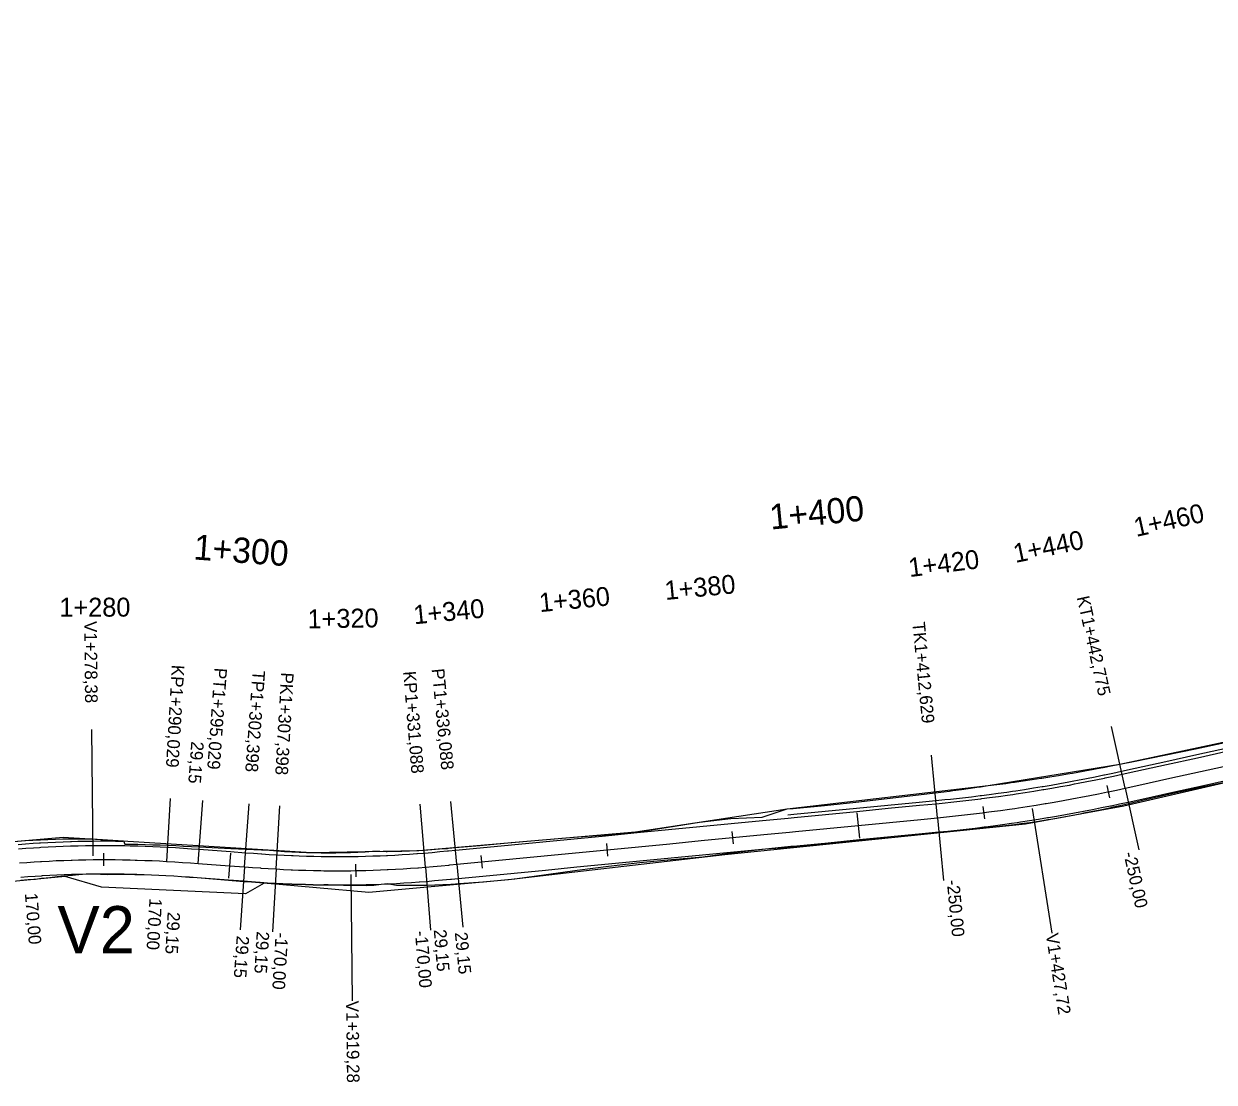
# Model space of a CAD drawing. Extents: x -636600 to -628587, y -1090963 to -1085869.
# Drawn here: x -634006.6 to -633817.9, y -1089449.3 to -1089281.6 of the extents above; entities that cross this region are included whole.
import ezdxf

# ---------------------------------------------------------------- set-up
doc = ezdxf.new("R2010")
doc.units = 0
for name, color, linetype in [('01_PARCELY_NÁVRH_PC', 7, 'Continuous'), ('03_PC_OBJEKTY_NÁVRH', 7, 'Continuous'), ('dno příkopu', 7, 'Continuous'), ('HEKTOMETRY100', 7, 'Continuous'), ('HEKTOMETRY20', 7, 'Continuous'), ('HL_BODY', 7, 'Continuous'), ('POLOMERY', 7, 'Continuous'), ('situace_osa', 7, 'Continuous'), ('situace_těleso', 7, 'Continuous'), ('situace_vozovka', 7, 'Continuous'), ('VRCHOLY', 7, 'Continuous')]:
    doc.layers.add(name, color=color, linetype=linetype)

msp = doc.modelspace()

# ---------------------------------------------------------------- linework, layer by layer
at = {"layer": '01_PARCELY_NÁVRH_PC'}
for points in [[(-634103.9, -1089419.55), (-634000.36, -1089410.49), (-633960.99, -1089412.95), (-633943.98, -1089412.6), (-633909.64, -1089409.67), (-633885.57, -1089406.01), (-633853.75, -1089402.34), (-633832.85, -1089398.94), (-633799.12, -1089391.77), (-633783.13, -1089387.75), (-633755.75, -1089378.34), (-633672.51, -1089347.22), (-633662.62, -1089342.52), (-633643.61, -1089332.07), (-633633.59, -1089327.63), (-633598.11, -1089315.12), (-633586.88, -1089310.55), (-633575.45, -1089304.31), (-633538.21, -1089281.62)], [(-633542.71, -1089289.87), (-633580.4, -1089312.77), (-633588.21, -1089316.5), (-633632.76, -1089332.36), (-633641.37, -1089336.22), (-633665.47, -1089349.24), (-633670.13, -1089353.9), (-633687.51, -1089361.23), (-633694.12, -1089361.51), (-633765.25, -1089388.16), (-633784.63, -1089394.62), (-633832.24, -1089405.6), (-633847.83, -1089408.44), (-633895.46, -1089413.28), (-633929.79, -1089417.29), (-633951.89, -1089419.25), (-633968.5, -1089417.82), (-633971.45, -1089419.48), (-633994.3, -1089418.42), (-634000.04, -1089416.76), (-634012.79, -1089417.95)]]:
    msp.add_lwpolyline(points, dxfattribs=at)
at = {"layer": 'dno příkopu'}
for points in [[(-633885.47, -1089406.97), (-633884.56, -1089406.88), (-633879.58, -1089406.4), (-633874.6, -1089405.92), (-633869.63, -1089405.44), (-633864.65, -1089404.96), (-633862.03, -1089404.7), (-633860.62, -1089404.56), (-633859.7, -1089404.47), (-633859.21, -1089404.41), (-633857.8, -1089404.26), (-633856.39, -1089404.09), (-633854.98, -1089403.92), (-633854.79, -1089403.89), (-633853.57, -1089403.74), (-633852.16, -1089403.55), (-633850.76, -1089403.35), (-633849.89, -1089403.22), (-633849.35, -1089403.15), (-633847.95, -1089402.93), (-633846.55, -1089402.71), (-633845.15, -1089402.48), (-633845, -1089402.46), (-633843.75, -1089402.24), (-633842.35, -1089402), (-633840.95, -1089401.74), (-633840.14, -1089401.59), (-633839.56, -1089401.48), (-633838.16, -1089401.21), (-633836.77, -1089400.93), (-633835.38, -1089400.65), (-633835.29, -1089400.63), (-633833.99, -1089400.35), (-633832.6, -1089400.05), (-633830.43, -1089399.57), (-633825.55, -1089398.5), (-633820.66, -1089397.42), (-633815.78, -1089396.35)], [(-634007.5, -1089411.66), (-634006.32, -1089411.57), (-634005.13, -1089411.48), (-634004.12, -1089411.42), (-634003.94, -1089411.41), (-634002.76, -1089411.34), (-634001.57, -1089411.29), (-634000.38, -1089411.24), (-633999.2, -1089411.19), (-633999.04, -1089411.19), (-633998.01, -1089411.16), (-633996.82, -1089411.14), (-633995.63, -1089411.12), (-633994.45, -1089411.11), (-633993.96, -1089411.11), (-633993.26, -1089411.11), (-633992.07, -1089411.12), (-633990.88, -1089411.13)]]:
    msp.add_lwpolyline(points, dxfattribs=at)
at = {"layer": 'HEKTOMETRY100'}
for points in [[(-633874.53, -1089406.66), (-633874.15, -1089410.65)], [(-633973.84, -1089413.04), (-633974.13, -1089417.03)]]:
    msp.add_lwpolyline(points, dxfattribs=at)
at = {"layer": 'HEKTOMETRY20'}
for points in [[(-633834.93, -1089402.34), (-633834.52, -1089404.3)], [(-633854.57, -1089405.63), (-633854.32, -1089407.61)], [(-633894.34, -1089409.59), (-633894.15, -1089411.58)], [(-633914.25, -1089411.51), (-633914.06, -1089413.5)], [(-633993.95, -1089413.06), (-633993.95, -1089415.06)], [(-633934.16, -1089413.43), (-633933.96, -1089415.43)], [(-633954.02, -1089414.81), (-633953.99, -1089416.81)]]:
    msp.add_lwpolyline(points, dxfattribs=at)
at = {"layer": 'HL_BODY'}
for points in [[(-633832.01, -1089402.74), (-633834.16, -1089392.97)], [(-633861.77, -1089407.44), (-633862.73, -1089397.49)], [(-633983.93, -1089414.34), (-633983.35, -1089404.36)], [(-633978.94, -1089414.68), (-633978.22, -1089404.7)], [(-633971.59, -1089415.21), (-633970.87, -1089405.24)], [(-633966.6, -1089415.55), (-633966.03, -1089405.56)], [(-633942.93, -1089415.26), (-633943.75, -1089405.3)], [(-633937.95, -1089414.81), (-633938.92, -1089404.85)]]:
    msp.add_lwpolyline(points, dxfattribs=at)
at = {"layer": 'POLOMERY'}
for points in [[(-633983.93, -1089414.34), (-633983.35, -1089404.36)], [(-633832.01, -1089402.74), (-633829.86, -1089412.5)], [(-633978.94, -1089414.68), (-633978.22, -1089404.7)], [(-633861.77, -1089407.44), (-633860.81, -1089417.39)], [(-633971.59, -1089415.21), (-633972.31, -1089425.18)], [(-633966.6, -1089415.55), (-633967.18, -1089425.53)], [(-633942.93, -1089415.26), (-633942.12, -1089425.23)], [(-633937.95, -1089414.81), (-633936.99, -1089424.76)]]:
    msp.add_lwpolyline(points, dxfattribs=at)
at = {"layer": 'situace_osa'}
msp.add_lwpolyline([(-634007.26, -1089414.6), (-634006.1, -1089414.51), (-634004.94, -1089414.43), (-634003.95, -1089414.37), (-634003.77, -1089414.36), (-634002.6, -1089414.29), (-634001.44, -1089414.23), (-634000.27, -1089414.18), (-633999.1, -1089414.14), (-633998.95, -1089414.14), (-633997.94, -1089414.11), (-633996.77, -1089414.09), (-633995.6, -1089414.07), (-633994.43, -1089414.06), (-633993.95, -1089414.06), (-633993.27, -1089414.06), (-633992.1, -1089414.07), (-633990.93, -1089414.08), (-633990.64, -1089414.09), (-633989.76, -1089414.1), (-633988.95, -1089414.13), (-633988.6, -1089414.14), (-633987.43, -1089414.18), (-633986.26, -1089414.22), (-633985.1, -1089414.28), (-633983.96, -1089414.34), (-633983.93, -1089414.34), (-633982.68, -1089414.42), (-633981.44, -1089414.5), (-633980.19, -1089414.59), (-633978.97, -1089414.68), (-633978.94, -1089414.68), (-633973.98, -1089415.04), (-633971.59, -1089415.21), (-633970.34, -1089415.3), (-633969.1, -1089415.39), (-633969, -1089415.4), (-633967.85, -1089415.47), (-633966.6, -1089415.55), (-633965.42, -1089415.61), (-633964.24, -1089415.67), (-633964, -1089415.68), (-633963.05, -1089415.72), (-633961.87, -1089415.76), (-633960.69, -1089415.79), (-633959.5, -1089415.81), (-633959.01, -1089415.82), (-633958.32, -1089415.82), (-633957.13, -1089415.83), (-633955.95, -1089415.83), (-633954.76, -1089415.82), (-633954.01, -1089415.81), (-633953.58, -1089415.8), (-633952.39, -1089415.77), (-633951.21, -1089415.74), (-633950.03, -1089415.7), (-633949.01, -1089415.65), (-633948.84, -1089415.64), (-633947.66, -1089415.58), (-633946.48, -1089415.52), (-633945.3, -1089415.44), (-633944.11, -1089415.36), (-633944.02, -1089415.35), (-633942.93, -1089415.26), (-633941.69, -1089415.16), (-633940.44, -1089415.04), (-633939.2, -1089414.93), (-633939.04, -1089414.91), (-633937.95, -1089414.81), (-633934.06, -1089414.43), (-633929.08, -1089413.95), (-633924.11, -1089413.47), (-633919.13, -1089412.99), (-633914.15, -1089412.51), (-633909.18, -1089412.02), (-633904.2, -1089411.54), (-633899.22, -1089411.06), (-633894.25, -1089410.58), (-633889.27, -1089410.1), (-633885.21, -1089409.71), (-633884.29, -1089409.62), (-633879.32, -1089409.14), (-633874.34, -1089408.66), (-633869.36, -1089408.17), (-633864.39, -1089407.69), (-633861.77, -1089407.44), (-633860.34, -1089407.3), (-633859.41, -1089407.2), (-633858.91, -1089407.15), (-633857.49, -1089406.99), (-633856.06, -1089406.82), (-633854.64, -1089406.65), (-633854.44, -1089406.62), (-633853.21, -1089406.46), (-633851.79, -1089406.27), (-633850.37, -1089406.07), (-633849.49, -1089405.95), (-633848.95, -1089405.86), (-633847.53, -1089405.65), (-633846.11, -1089405.43), (-633844.69, -1089405.19), (-633844.55, -1089405.17), (-633843.28, -1089404.95), (-633841.86, -1089404.7), (-633840.45, -1089404.45), (-633839.63, -1089404.29), (-633839.04, -1089404.18), (-633837.63, -1089403.91), (-633836.22, -1089403.63), (-633834.82, -1089403.34), (-633834.72, -1089403.32), (-633833.41, -1089403.04), (-633832.01, -1089402.74), (-633829.84, -1089402.26), (-633824.95, -1089401.18), (-633820.07, -1089400.11), (-633815.19, -1089399.03)], dxfattribs=at)
at = {"layer": 'situace_těleso'}
for points in [[(-634007.54, -1089411.14), (-634006.35, -1089411.05), (-634005.16, -1089410.98), (-634004.15, -1089410.93), (-634003.97, -1089410.92), (-634002.78, -1089410.87), (-634001.59, -1089410.83), (-634000.4, -1089410.79), (-633999.21, -1089410.77), (-633999.06, -1089410.77), (-633998.02, -1089410.76), (-633996.83, -1089410.76), (-633995.82, -1089410.78), (-633990.77, -1089411.09), (-633990.59, -1089411.59), (-633989.71, -1089411.6), (-633988.88, -1089411.62), (-633988.52, -1089411.63), (-633987.34, -1089411.66), (-633986.15, -1089411.7), (-633984.97, -1089411.74), (-633983.81, -1089411.79), (-633983.78, -1089411.79), (-633982.52, -1089411.85), (-633981.26, -1089411.92), (-633980, -1089411.98), (-633978.78, -1089412.04), (-633978.75, -1089412.04), (-633973.78, -1089412.28), (-633971.39, -1089412.39), (-633970.14, -1089412.45), (-633968.9, -1089412.51), (-633968.8, -1089412.51), (-633967.66, -1089412.57), (-633966.44, -1089412.67), (-633965.27, -1089412.76), (-633964.11, -1089412.83), (-633963.88, -1089412.84), (-633962.95, -1089412.88), (-633961.78, -1089412.93), (-633960.62, -1089412.96), (-633959.46, -1089412.98), (-633958.97, -1089412.98), (-633958.29, -1089412.99), (-633957.13, -1089412.98), (-633955.96, -1089412.96), (-633954.8, -1089412.93), (-633954.05, -1089412.9), (-633953.63, -1089412.88), (-633952.47, -1089412.82), (-633951.31, -1089412.75), (-633950.14, -1089412.75), (-633949.14, -1089412.77), (-633948.98, -1089412.76), (-633947.81, -1089412.74), (-633946.65, -1089412.71), (-633945.48, -1089412.67), (-633944.32, -1089412.62), (-633944.22, -1089412.61), (-633943.16, -1089412.55), (-633941.93, -1089412.47), (-633940.69, -1089412.38), (-633939.45, -1089412.28), (-633939.29, -1089412.27), (-633938.21, -1089412.17), (-633934.31, -1089411.82), (-633929.34, -1089411.35), (-633924.35, -1089410.93), (-633919.37, -1089410.5), (-633914.38, -1089410.13), (-633909.4, -1089409.71), (-633904.45, -1089408.92), (-633899.51, -1089408.13), (-633894.54, -1089407.56), (-633889.54, -1089407.35), (-633885.57, -1089406.01), (-633884.65, -1089405.94), (-633879.67, -1089405.5), (-633874.7, -1089404.95), (-633869.73, -1089404.37), (-633864.76, -1089403.79), (-633862.15, -1089403.48), (-633860.75, -1089403.31), (-633859.84, -1089403.2), (-633859.35, -1089403.13), (-633857.95, -1089402.94), (-633856.55, -1089402.75), (-633855.15, -1089402.54), (-633854.96, -1089402.51), (-633853.75, -1089402.34), (-633852.35, -1089402.17), (-633850.95, -1089401.98), (-633850.09, -1089401.87), (-633849.55, -1089401.8), (-633848.16, -1089401.6), (-633846.76, -1089401.39), (-633845.36, -1089401.17), (-633845.22, -1089401.15), (-633843.97, -1089400.95), (-633842.58, -1089400.71), (-633841.18, -1089400.48), (-633840.37, -1089400.35), (-633839.79, -1089400.25), (-633838.4, -1089400), (-633837.01, -1089399.75), (-633835.62, -1089399.49), (-633835.53, -1089399.47), (-633834.23, -1089399.22), (-633832.85, -1089398.94), (-633830.67, -1089398.5), (-633825.76, -1089397.51), (-633820.86, -1089396.53), (-633815.98, -1089395.46)], [(-633814.64, -1089401.54), (-633819.54, -1089402.51), (-633824.42, -1089403.61), (-633829.29, -1089404.72), (-633831.46, -1089405.22), (-633832.88, -1089405.53), (-633834.2, -1089405.82), (-633834.3, -1089405.84), (-633835.71, -1089406.15), (-633837.13, -1089406.44), (-633838.56, -1089406.72), (-633839.15, -1089406.84), (-633839.98, -1089407), (-633841.41, -1089407.27), (-633842.83, -1089407.53), (-633844.12, -1089407.75), (-633844.26, -1089407.77), (-633845.69, -1089408.01), (-633847.13, -1089408.24), (-633848.57, -1089408.41), (-633849.12, -1089408.48), (-633850.01, -1089408.6), (-633851.45, -1089408.77), (-633852.89, -1089408.94), (-633854.13, -1089409.07), (-633854.33, -1089409.09), (-633855.77, -1089409.24), (-633857.21, -1089409.38), (-633858.66, -1089409.52), (-633859.16, -1089409.56), (-633860.1, -1089409.64), (-633861.54, -1089409.76), (-633864.17, -1089409.96), (-633869.14, -1089410.48), (-633874.11, -1089411.06), (-633879.08, -1089411.61), (-633884.06, -1089412.06), (-633884.98, -1089412.13), (-633889.05, -1089412.39), (-633894.02, -1089412.97), (-633898.97, -1089413.69), (-633903.95, -1089414.11), (-633908.93, -1089414.57), (-633913.9, -1089415.13), (-633918.86, -1089415.78), (-633923.82, -1089416.48), (-633928.77, -1089417.18), (-633933.75, -1089417.64), (-633937.65, -1089417.92), (-633938.74, -1089417.99), (-633938.9, -1089418), (-633940.16, -1089418.07), (-633941.43, -1089418.12), (-633942.7, -1089418.16), (-633943.81, -1089418.18), (-633943.9, -1089418.18), (-633945.11, -1089418.18), (-633946.32, -1089418.17), (-633947.52, -1089418.15), (-633948.73, -1089417.96), (-633948.9, -1089417.92), (-633949.93, -1089418.02), (-633951.13, -1089418.17), (-633952.33, -1089418.21), (-633953.53, -1089418.19), (-633953.97, -1089418.19), (-633954.73, -1089418.17), (-633955.94, -1089418.15), (-633957.14, -1089418.12), (-633958.34, -1089418.08), (-633959.04, -1089418.08), (-633959.54, -1089418.1), (-633960.74, -1089418.08), (-633961.94, -1089418.02), (-633963.14, -1089417.99), (-633964.1, -1089417.98), (-633964.34, -1089417.97), (-633965.54, -1089417.96), (-633966.74, -1089417.93), (-633968, -1089417.86), (-633969.16, -1089417.76), (-633969.26, -1089417.75), (-633970.51, -1089417.66), (-633971.76, -1089417.57), (-633974.15, -1089417.36), (-633979.11, -1089416.96), (-633979.14, -1089416.96), (-633980.35, -1089416.87), (-633981.59, -1089416.78), (-633982.83, -1089416.7), (-633984.06, -1089416.63), (-633984.09, -1089416.63), (-633985.21, -1089416.57), (-633986.36, -1089416.52), (-633987.51, -1089416.48), (-633988.67, -1089416.45), (-633989.02, -1089416.45), (-633989.82, -1089416.43), (-633990.68, -1089416.42), (-633990.97, -1089416.44), (-633992.12, -1089416.44), (-633993.27, -1089416.45), (-633993.95, -1089416.44), (-633994.42, -1089416.41), (-633995.58, -1089416.36), (-633996.73, -1089416.36), (-633997.88, -1089416.46), (-633998.88, -1089416.56), (-633999.03, -1089416.57), (-634000.17, -1089416.68), (-634001.32, -1089416.8), (-634002.47, -1089416.93), (-634003.61, -1089417.06), (-634003.78, -1089417.08), (-634004.75, -1089417.2), (-634005.9, -1089417.26), (-634007.04, -1089417.36)]]:
    msp.add_lwpolyline(points, dxfattribs=at)
at = {"layer": 'situace_vozovka'}
for points in [[(-634007.44, -1089412.36), (-634006.26, -1089412.27), (-634005.08, -1089412.18), (-634004.08, -1089412.12), (-634003.9, -1089412.11), (-634002.72, -1089412.04), (-634001.54, -1089411.99), (-634000.36, -1089411.94), (-633999.18, -1089411.89), (-633999.02, -1089411.89), (-633997.99, -1089411.86), (-633996.81, -1089411.84), (-633995.63, -1089411.82), (-633994.44, -1089411.81), (-633993.96, -1089411.81), (-633993.26, -1089411.81), (-633992.08, -1089411.82), (-633990.89, -1089411.83), (-633990.6, -1089411.84), (-633989.71, -1089411.86), (-633988.89, -1089411.88), (-633988.53, -1089411.89), (-633987.35, -1089411.93), (-633986.16, -1089411.97), (-633984.98, -1089412.03), (-633983.83, -1089412.09), (-633983.8, -1089412.09), (-633982.54, -1089412.17), (-633981.28, -1089412.26), (-633980.03, -1089412.34), (-633978.81, -1089412.43), (-633978.78, -1089412.43), (-633973.82, -1089412.79), (-633971.43, -1089412.97), (-633970.18, -1089413.06), (-633968.94, -1089413.14), (-633968.84, -1089413.15), (-633967.71, -1089413.23), (-633966.47, -1089413.3), (-633965.31, -1089413.36), (-633964.14, -1089413.42), (-633963.91, -1089413.43), (-633962.97, -1089413.47), (-633961.8, -1089413.51), (-633960.63, -1089413.54), (-633959.47, -1089413.56), (-633958.98, -1089413.57), (-633958.3, -1089413.57), (-633957.13, -1089413.58), (-633955.96, -1089413.58), (-633954.79, -1089413.57), (-633954.04, -1089413.56), (-633953.62, -1089413.55), (-633952.45, -1089413.52), (-633951.28, -1089413.49), (-633950.12, -1089413.45), (-633949.11, -1089413.4), (-633948.95, -1089413.4), (-633947.78, -1089413.34), (-633946.61, -1089413.27), (-633945.45, -1089413.2), (-633944.28, -1089413.11), (-633944.19, -1089413.11), (-633943.12, -1089413.02), (-633941.89, -1089412.92), (-633940.65, -1089412.8), (-633939.41, -1089412.69), (-633939.25, -1089412.67), (-633938.17, -1089412.57), (-633934.28, -1089412.19), (-633929.3, -1089411.71), (-633924.32, -1089411.23), (-633919.35, -1089410.75), (-633914.37, -1089410.27), (-633909.39, -1089409.78), (-633904.42, -1089409.3), (-633899.44, -1089408.82), (-633894.46, -1089408.34), (-633889.49, -1089407.86), (-633885.43, -1089407.47), (-633884.51, -1089407.38), (-633879.53, -1089406.9), (-633874.56, -1089406.42), (-633869.58, -1089405.93), (-633864.6, -1089405.45), (-633861.99, -1089405.2), (-633860.57, -1089405.06), (-633859.65, -1089404.96), (-633859.15, -1089404.91), (-633857.74, -1089404.75), (-633856.33, -1089404.59), (-633854.92, -1089404.41), (-633854.73, -1089404.39), (-633853.51, -1089404.23), (-633852.1, -1089404.04), (-633850.69, -1089403.85), (-633849.82, -1089403.72), (-633849.28, -1089403.64), (-633847.87, -1089403.43), (-633846.47, -1089403.2), (-633845.06, -1089402.97), (-633844.92, -1089402.95), (-633843.66, -1089402.74), (-633842.26, -1089402.49), (-633840.86, -1089402.24), (-633840.04, -1089402.08), (-633839.46, -1089401.97), (-633838.07, -1089401.7), (-633836.67, -1089401.42), (-633835.28, -1089401.14), (-633835.18, -1089401.12), (-633833.88, -1089400.84), (-633832.49, -1089400.54), (-633830.32, -1089400.06), (-633825.44, -1089398.99), (-633820.56, -1089397.91), (-633815.67, -1089396.83)], [(-634007.09, -1089416.84), (-634005.94, -1089416.75), (-634004.79, -1089416.67), (-634003.81, -1089416.61), (-634003.64, -1089416.6), (-634002.49, -1089416.54), (-634001.34, -1089416.48), (-634000.18, -1089416.43), (-633999.03, -1089416.39), (-633998.88, -1089416.39), (-633997.88, -1089416.36), (-633996.73, -1089416.34), (-633995.58, -1089416.32), (-633994.42, -1089416.31), (-633993.95, -1089416.31), (-633993.27, -1089416.31), (-633992.12, -1089416.32), (-633990.97, -1089416.33), (-633990.68, -1089416.34), (-633989.82, -1089416.35), (-633989.02, -1089416.37), (-633988.66, -1089416.38), (-633987.51, -1089416.42), (-633986.36, -1089416.47), (-633985.21, -1089416.52), (-633984.09, -1089416.59), (-633984.06, -1089416.59), (-633982.83, -1089416.66), (-633981.59, -1089416.74), (-633980.35, -1089416.83), (-633979.13, -1089416.92), (-633979.1, -1089416.92), (-633974.15, -1089417.28), (-633971.75, -1089417.45), (-633970.5, -1089417.55), (-633969.25, -1089417.63), (-633969.15, -1089417.64), (-633967.99, -1089417.72), (-633966.73, -1089417.79), (-633965.53, -1089417.86), (-633964.33, -1089417.92), (-633964.1, -1089417.93), (-633963.14, -1089417.96), (-633961.94, -1089418), (-633960.74, -1089418.04), (-633959.54, -1089418.06), (-633959.04, -1089418.07), (-633958.34, -1089418.07), (-633957.14, -1089418.08), (-633955.94, -1089418.08), (-633954.74, -1089418.07), (-633953.97, -1089418.06), (-633953.54, -1089418.05), (-633952.34, -1089418.02), (-633951.14, -1089417.99), (-633949.94, -1089417.94), (-633948.91, -1089417.9), (-633948.74, -1089417.89), (-633947.54, -1089417.83), (-633946.34, -1089417.76), (-633945.14, -1089417.69), (-633943.95, -1089417.6), (-633943.85, -1089417.59), (-633942.75, -1089417.51), (-633941.49, -1089417.4), (-633940.23, -1089417.28), (-633938.98, -1089417.17), (-633938.82, -1089417.15), (-633937.74, -1089417.05), (-633933.84, -1089416.67), (-633928.87, -1089416.19), (-633923.89, -1089415.71), (-633918.91, -1089415.23), (-633913.94, -1089414.74), (-633908.96, -1089414.26), (-633903.98, -1089413.78), (-633899.01, -1089413.3), (-633894.03, -1089412.82), (-633889.05, -1089412.34), (-633884.99, -1089411.95), (-633884.08, -1089411.86), (-633879.1, -1089411.38), (-633874.12, -1089410.9), (-633869.15, -1089410.41), (-633864.17, -1089409.93), (-633861.55, -1089409.68), (-633860.11, -1089409.54), (-633859.17, -1089409.44), (-633858.67, -1089409.38), (-633857.23, -1089409.22), (-633855.79, -1089409.06), (-633854.35, -1089408.88), (-633854.16, -1089408.85), (-633852.92, -1089408.69), (-633851.48, -1089408.5), (-633850.05, -1089408.3), (-633849.16, -1089408.17), (-633848.61, -1089408.09), (-633847.18, -1089407.87), (-633845.75, -1089407.65), (-633844.32, -1089407.41), (-633844.18, -1089407.39), (-633842.89, -1089407.17), (-633841.47, -1089406.92), (-633840.04, -1089406.66), (-633839.21, -1089406.51), (-633838.62, -1089406.39), (-633837.2, -1089406.12), (-633835.78, -1089405.83), (-633834.36, -1089405.54), (-633834.26, -1089405.52), (-633832.94, -1089405.24), (-633831.53, -1089404.94), (-633829.35, -1089404.46), (-633824.47, -1089403.38), (-633819.59, -1089402.3), (-633814.7, -1089401.23)]]:
    msp.add_lwpolyline(points, dxfattribs=at)
at = {"layer": 'VRCHOLY'}
for points in [[(-633995.61, -1089413.47), (-633995.83, -1089393.47)], [(-633846.75, -1089405.99), (-633843.63, -1089425.74)], [(-633954.76, -1089416.43), (-633954.52, -1089436.43)]]:
    msp.add_lwpolyline(points, dxfattribs=at)

# ---------------------------------------------------------------- texts
at = {"layer": '03_PC_OBJEKTY_NÁVRH'}
msp.add_text('V2', height=7.5, dxfattribs=at).set_placement((-634001.25, -1089428.93))
at = {"layer": 'HEKTOMETRY100'}
for s, rotation, p in [('1+400', 5.523, (-633888.19, -1089361.77)), ('1+300', 355.8535, (-633979.76, -1089366.49))]:
    msp.add_text(s, height=4, rotation=rotation, dxfattribs=at).set_placement(p)
at = {"layer": 'HEKTOMETRY20'}
for s, rotation, p in [('1+460', 12.4319, (-633830.27, -1089362.93)), ('1+440', 11.7959, (-633849.4, -1089367.06)), ('1+420', 7.2122, (-633866.18, -1089369.3)), ('1+380', 5.523, (-633904.88, -1089372.93)), ('1+280', 0.0761, (-634000.96, -1089375.57)), ('1+360', 5.523, (-633924.78, -1089374.85)), ('1+320', 0.9433, (-633961.6, -1089377.43)), ('1+340', 5.523, (-633944.69, -1089376.78))]:
    msp.add_text(s, height=3, rotation=rotation, dxfattribs=at).set_placement(p)
at = {"layer": 'HL_BODY'}
for s, rotation, p in [('KT1+442,775', 282.4319, (-633839.7, -1089372.51)), ('TK1+412,629', 275.523, (-633865.76, -1089376.5)), ('KP1+290,029', 266.6961, (-633983.13, -1089383.16)), ('PT1+295,029', 265.8535, (-633976.36, -1089383.62)), ('TP1+302,398', 265.8535, (-633970.33, -1089384.04)), ('PK1+307,398', 266.6961, (-633965.8, -1089384.36)), ('KP1+331,088', 274.6804, (-633946.47, -1089384.27)), ('PT1+336,088', 275.523, (-633941.95, -1089383.87))]:
    msp.add_text(s, height=2, rotation=rotation, dxfattribs=at).set_placement(p)
at = {"layer": 'POLOMERY'}
for s, rotation, p in [('29,15', 265.8535, (-633980.04, -1089395.27)), ('-250,00', 282.4319, (-633832.3, -1089413.04)), ('-250,00', 275.523, (-633860.31, -1089417.35)), ('170,00', 274.5673, (-634006.43, -1089419.42)), ('170,00', 266.6961, (-633986.67, -1089420.16)), ('29,15', 266.6961, (-633983.79, -1089422.31)), ('29,15', 274.6804, (-633941.62, -1089425.19)), ('29,15', 265.8535, (-633972.84, -1089426.08)), ('29,15', 266.6961, (-633969.67, -1089425.39)), ('-170,00', 266.6961, (-633966.68, -1089425.56)), ('-170,00', 274.6804, (-633944.61, -1089425.43)), ('29,15', 275.523, (-633938.28, -1089425.64))]:
    msp.add_text(s, height=2, rotation=rotation, dxfattribs=at).set_placement(p)
at = {"layer": 'VRCHOLY'}
for s, rotation, p in [('V1+278,38', 270.6317, (-633997.02, -1089376.27)), ('V1+427,72', 278.9774, (-633844.61, -1089425.9)), ('V1+319,28', 270.6882, (-633955.52, -1089436.44))]:
    msp.add_text(s, height=2, rotation=rotation, dxfattribs=at).set_placement(p)

doc.saveas('drawing.dxf')
